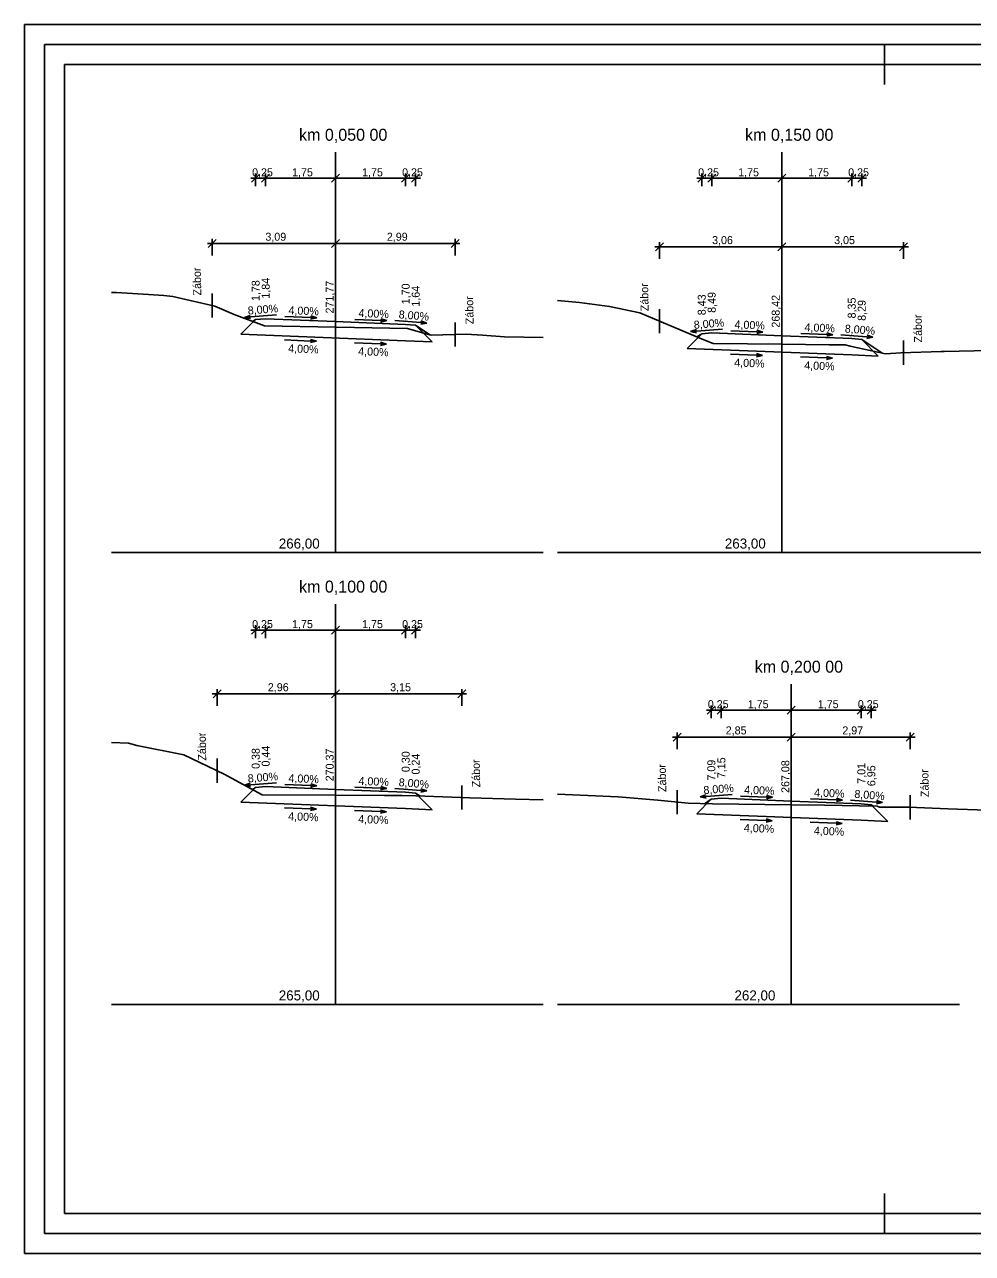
# Model space of a CAD drawing. Extents: x -763510.2 to -763467.2, y -1048902.9 to -1048872.2.
# Drawn here: x -763510.21 to -763486.51, y -1048902.88 to -1048872.18 of the extents above; entities that cross this region are included whole.
import ezdxf

# ---------------------------------------------------------------- set-up
doc = ezdxf.new("R2010")
doc.units = 0
for name, color, linetype in [('C3D-KORIDOR-SPOJNICE', 7, 'Continuous'), ('C3D-POPIS', 7, 'Continuous'), ('C3D-PR-POPIS-TEREN', 7, 'Continuous'), ('C3D-PR-TEREN', 7, 'Continuous'), ('C3D-ZOBPR-NADPIS', 7, 'Continuous'), ('C3D-ZOBPR-OSY', 7, 'Continuous'), ('C3D-ZOBPR-OSY-NADPIS', 7, 'Continuous'), ('Default', 7, 'Continuous'), ('U_formát', 7, 'Continuous'), ('U_rozvržení_rámeček', 7, 'Continuous'), ('Z_Pomocná', 7, 'Continuous')]:
    doc.layers.add(name, color=color, linetype=linetype)

# ---------------------------------------------------------------- blocks, each defined once
blk = doc.blocks.new('_Oblique')
at = {"layer": 'Default'}
blk.add_line((-0.5, -0.5), (0.5, 0.5), dxfattribs=at)
blk = doc.blocks.new('_Open30')
at = {"layer": 'Default'}
for p, q in [((-1, 0.27), (0, 0)), ((0, 0), (-1, -0.27)), ((0, 0), (-1, 0))]:
    blk.add_line(p, q, dxfattribs=at)
blk = doc.blocks.new('U1096')
at = {"layer": 'Default'}
for p, q in [((-420, 0), (-420, -10)), ((-210, 0), (-210, -10)), ((-420, -297), (-420, -287)), ((-210, -297), (-210, -287)), ((-420, -297), (-410, -297))]:
    blk.add_line(p, q, dxfattribs=at)
blk.add_lwpolyline([(0, -297), (0, 0), (-420, 0), (-420, -297)], close=True, dxfattribs=at)
at = {"layer": 'U_formát'}
for points in [[(-425, 5), (5, 5), (5, -302), (-425, -302)], [(-5, -292), (-5, -5), (-415, -5), (-415, -292)]]:
    blk.add_lwpolyline(points, close=True, dxfattribs=at)

msp = doc.modelspace()

# ---------------------------------------------------------------- linework, layer by layer
at = {"layer": 'C3D-KORIDOR-SPOJNICE'}
for p, q in [((-763504.434, -1048879.555), (-763504.8, -1048879.92)), ((-763504.434, -1048879.555), (-763504.507, -1048879.604)), ((-763504.184, -1048879.535), (-763504.434, -1048879.555)), ((-763502.434, -1048879.605), (-763504.184, -1048879.535)), ((-763502.434, -1048879.605), (-763500.684, -1048879.675)), ((-763504.8, -1048879.92), (-763500.684, -1048880.085)), ((-763500.684, -1048879.675), (-763500.434, -1048879.695)), ((-763500.434, -1048879.695), (-763500.018, -1048880.112)), ((-763500.434, -1048879.695), (-763500.077, -1048879.933)), ((-763493.283, -1048879.909), (-763493.649, -1048880.275)), ((-763493.283, -1048879.909), (-763493.403, -1048879.989)), ((-763493.033, -1048879.889), (-763493.283, -1048879.909)), ((-763491.283, -1048879.959), (-763493.033, -1048879.889)), ((-763500.018, -1048880.112), (-763500.684, -1048880.085)), ((-763491.283, -1048879.959), (-763489.533, -1048880.029)), ((-763489.533, -1048880.029), (-763489.283, -1048880.049)), ((-763489.283, -1048880.049), (-763488.867, -1048880.466)), ((-763489.283, -1048880.049), (-763488.776, -1048880.388)), ((-763493.649, -1048880.275), (-763489.533, -1048880.439)), ((-763488.867, -1048880.466), (-763489.533, -1048880.439)), ((-763504.434, -1048891.243), (-763504.8, -1048891.609)), ((-763504.434, -1048891.243), (-763504.514, -1048891.296)), ((-763504.184, -1048891.223), (-763504.434, -1048891.243)), ((-763502.434, -1048891.293), (-763504.184, -1048891.223)), ((-763502.434, -1048891.293), (-763500.684, -1048891.363)), ((-763500.684, -1048891.363), (-763500.434, -1048891.383)), ((-763500.434, -1048891.383), (-763500.018, -1048891.8)), ((-763500.434, -1048891.383), (-763500.327, -1048891.455)), ((-763493.042, -1048891.534), (-763493.408, -1048891.9)), ((-763493.042, -1048891.534), (-763493.214, -1048891.649)), ((-763492.792, -1048891.514), (-763493.042, -1048891.534)), ((-763491.042, -1048891.584), (-763492.792, -1048891.514)), ((-763491.042, -1048891.584), (-763489.292, -1048891.654)), ((-763504.8, -1048891.609), (-763500.684, -1048891.773)), ((-763500.018, -1048891.8), (-763500.684, -1048891.773)), ((-763493.408, -1048891.9), (-763489.292, -1048892.064)), ((-763489.292, -1048891.654), (-763489.042, -1048891.674)), ((-763489.042, -1048891.674), (-763488.626, -1048892.091)), ((-763489.042, -1048891.674), (-763488.987, -1048891.711)), ((-763488.626, -1048892.091), (-763489.292, -1048892.064))]:
    msp.add_line(p, q, dxfattribs=at)
at = {"layer": 'C3D-POPIS'}
for p, q in [((-763504.434, -1048876.224), (-763504.434, -1048875.904)), ((-763504.184, -1048876.224), (-763504.184, -1048875.904)), ((-763502.434, -1048876.224), (-763502.434, -1048875.904)), ((-763500.684, -1048876.224), (-763500.684, -1048875.904)), ((-763500.434, -1048876.224), (-763500.434, -1048875.904)), ((-763493.283, -1048876.224), (-763493.283, -1048875.904)), ((-763493.033, -1048876.224), (-763493.033, -1048875.904)), ((-763491.283, -1048876.224), (-763491.283, -1048875.904)), ((-763489.533, -1048876.224), (-763489.533, -1048875.904)), ((-763489.283, -1048876.224), (-763489.283, -1048875.904)), ((-763504.554, -1048876.024), (-763502.314, -1048876.024)), ((-763502.554, -1048876.024), (-763500.314, -1048876.024)), ((-763493.403, -1048876.024), (-763491.163, -1048876.024)), ((-763491.403, -1048876.024), (-763489.163, -1048876.024)), ((-763504.434, -1048887.513), (-763504.434, -1048887.193)), ((-763504.184, -1048887.513), (-763504.184, -1048887.193)), ((-763502.434, -1048887.513), (-763502.434, -1048887.193)), ((-763500.684, -1048887.513), (-763500.684, -1048887.193)), ((-763500.434, -1048887.513), (-763500.434, -1048887.193)), ((-763504.554, -1048887.313), (-763502.314, -1048887.313)), ((-763502.554, -1048887.313), (-763500.314, -1048887.313)), ((-763493.162, -1048889.313), (-763490.922, -1048889.313)), ((-763493.042, -1048889.513), (-763493.042, -1048889.193)), ((-763492.792, -1048889.513), (-763492.792, -1048889.193)), ((-763491.162, -1048889.313), (-763488.922, -1048889.313)), ((-763491.042, -1048889.513), (-763491.042, -1048889.193)), ((-763489.292, -1048889.513), (-763489.292, -1048889.193)), ((-763489.042, -1048889.513), (-763489.042, -1048889.193))]:
    msp.add_line(p, q, dxfattribs=at)
for points in [[(-763504.564, -1048879.49), (-763503.916, -1048879.438)], [(-763503.056, -1048879.505), (-763503.706, -1048879.479)], [(-763501.306, -1048879.575), (-763501.956, -1048879.549)], [(-763500.304, -1048879.63), (-763500.952, -1048879.578)], [(-763493.413, -1048879.844), (-763492.765, -1048879.793)], [(-763491.905, -1048879.859), (-763492.555, -1048879.833)], [(-763490.155, -1048879.929), (-763490.805, -1048879.903)], [(-763503.063, -1048880.09), (-763503.713, -1048880.064)], [(-763501.313, -1048880.16), (-763501.963, -1048880.134)], [(-763489.153, -1048879.984), (-763489.801, -1048879.933)], [(-763491.912, -1048880.444), (-763492.562, -1048880.418)], [(-763490.162, -1048880.514), (-763490.812, -1048880.488)], [(-763504.564, -1048891.179), (-763503.916, -1048891.127)], [(-763503.056, -1048891.193), (-763503.706, -1048891.167)], [(-763501.306, -1048891.263), (-763501.956, -1048891.237)], [(-763500.304, -1048891.319), (-763500.952, -1048891.267)], [(-763493.173, -1048891.469), (-763492.525, -1048891.418)], [(-763491.665, -1048891.484), (-763492.314, -1048891.458)], [(-763489.915, -1048891.554), (-763490.564, -1048891.528)], [(-763488.912, -1048891.609), (-763489.56, -1048891.558)], [(-763503.063, -1048891.778), (-763503.713, -1048891.752)], [(-763501.313, -1048891.848), (-763501.963, -1048891.822)], [(-763491.672, -1048892.069), (-763492.321, -1048892.043)], [(-763489.922, -1048892.139), (-763490.571, -1048892.113)]]:
    msp.add_lwpolyline(points, dxfattribs=at)
at = {"layer": 'C3D-PR-TEREN'}
for points in [[(-763508.038, -1048878.875), (-763507.915, -1048878.879), (-763507.116, -1048878.927), (-763506.733, -1048878.954), (-763506.504, -1048878.982), (-763505.458, -1048879.218), (-763504.973, -1048879.43), (-763504.211, -1048879.714), (-763502.434, -1048879.746), (-763501.963, -1048879.754), (-763500.634, -1048879.775), (-763500.266, -1048879.888), (-763500.042, -1048879.941), (-763499.171, -1048879.918), (-763498.762, -1048879.94), (-763498.214, -1048879.989), (-763497.246, -1048880.002)], [(-763496.887, -1048879.077), (-763496.334, -1048879.124), (-763495.584, -1048879.224), (-763494.83, -1048879.39), (-763493.229, -1048880.061), (-763492.998, -1048880.148), (-763491.283, -1048880.169), (-763490.093, -1048880.184), (-763489.693, -1048880.187), (-763489.569, -1048880.215), (-763488.688, -1048880.407), (-763488.306, -1048880.383), (-763487.299, -1048880.356), (-763487.225, -1048880.356), (-763486.095, -1048880.331)], [(-763508.038, -1048890.123), (-763507.615, -1048890.137), (-763507.403, -1048890.198), (-763506.228, -1048890.425), (-763505.223, -1048890.908), (-763504.27, -1048891.43), (-763502.434, -1048891.438), (-763501.211, -1048891.444), (-763500.78, -1048891.441), (-763500.43, -1048891.451), (-763499.08, -1048891.502), (-763497.94, -1048891.54), (-763497.246, -1048891.551)], [(-763496.887, -1048891.415), (-763495.367, -1048891.474), (-763494.381, -1048891.564), (-763493.619, -1048891.634), (-763493.016, -1048891.656), (-763491.042, -1048891.68), (-763490.216, -1048891.69), (-763488.9, -1048891.713), (-763488.84, -1048891.735), (-763488.575, -1048891.732), (-763488.102, -1048891.738), (-763487.13, -1048891.778), (-763485.901, -1048891.816), (-763485.569, -1048891.814)]]:
    msp.add_lwpolyline(points, dxfattribs=at)
at = {"layer": 'C3D-ZOBPR-OSY'}
for p, q in [((-763502.434, -1048885.374), (-763502.434, -1048875.374)), ((-763491.283, -1048885.374), (-763491.283, -1048875.374)), ((-763508.038, -1048885.374), (-763497.246, -1048885.374)), ((-763496.887, -1048885.374), (-763486.095, -1048885.374)), ((-763502.434, -1048896.663), (-763502.434, -1048886.663)), ((-763491.042, -1048896.663), (-763491.042, -1048888.663)), ((-763508.038, -1048896.663), (-763497.246, -1048896.663)), ((-763496.887, -1048896.663), (-763486.84, -1048896.663))]:
    msp.add_line(p, q, dxfattribs=at)
at = {"layer": 'Default'}
for p, q in [((-763502.434, -1048877.355), (-763502.434, -1048877.775)), ((-763502.434, -1048877.355), (-763502.434, -1048877.775)), ((-763491.283, -1048877.439), (-763491.283, -1048877.859)), ((-763491.283, -1048877.439), (-763491.283, -1048877.859)), ((-763505.641, -1048877.655), (-763502.314, -1048877.655)), ((-763505.521, -1048877.955), (-763505.521, -1048877.535)), ((-763502.554, -1048877.655), (-763499.327, -1048877.655)), ((-763499.447, -1048877.955), (-763499.447, -1048877.535)), ((-763494.458, -1048877.739), (-763491.163, -1048877.739)), ((-763494.338, -1048878.039), (-763494.338, -1048877.619)), ((-763491.403, -1048877.739), (-763488.114, -1048877.739)), ((-763488.234, -1048878.039), (-763488.234, -1048877.619)), ((-763505.398, -1048889.208), (-763505.398, -1048888.788)), ((-763502.434, -1048888.608), (-763502.434, -1048889.028)), ((-763502.434, -1048888.608), (-763502.434, -1048889.028)), ((-763499.283, -1048889.208), (-763499.283, -1048888.788)), ((-763505.518, -1048888.908), (-763502.314, -1048888.908)), ((-763502.554, -1048888.908), (-763499.163, -1048888.908)), ((-763491.042, -1048889.688), (-763491.042, -1048890.108)), ((-763491.042, -1048889.688), (-763491.042, -1048890.108)), ((-763494.015, -1048889.988), (-763490.922, -1048889.988)), ((-763493.895, -1048890.288), (-763493.895, -1048889.868)), ((-763491.162, -1048889.988), (-763487.948, -1048889.988)), ((-763488.068, -1048890.288), (-763488.068, -1048889.868))]:
    msp.add_line(p, q, dxfattribs=at)
at = {"layer": 'Z_Pomocná'}
for points in [[(-763505.521, -1048879.504), (-763505.521, -1048879.204), (-763505.521, -1048878.904)], [(-763494.338, -1048879.897), (-763494.338, -1048879.597), (-763494.338, -1048879.297)], [(-763499.447, -1048880.226), (-763499.447, -1048879.926), (-763499.447, -1048879.626)], [(-763488.234, -1048880.681), (-763488.234, -1048880.381), (-763488.234, -1048880.081)], [(-763505.398, -1048891.124), (-763505.398, -1048890.824), (-763505.398, -1048890.524)], [(-763499.283, -1048891.795), (-763499.283, -1048891.495), (-763499.283, -1048891.195)], [(-763493.895, -1048891.908), (-763493.895, -1048891.608), (-763493.895, -1048891.308)], [(-763488.068, -1048892.04), (-763488.068, -1048891.74), (-763488.068, -1048891.44)]]:
    msp.add_lwpolyline(points, dxfattribs=at)

# ---------------------------------------------------------------- block references
at = {"layer": 'C3D-POPIS'}
for name, p, xscale, yscale, rotation in [('_Oblique', (-763504.434, -1048876.024), 0.2, 0.20000000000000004, 180), ('_Oblique', (-763504.184, -1048876.024), 0.2, 0.20000000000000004, 180), ('_Oblique', (-763502.434, -1048876.024), 0.2, 0.20000000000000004, 180), ('_Oblique', (-763493.283, -1048876.024), 0.2, 0.20000000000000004, 180), ('_Oblique', (-763493.033, -1048876.024), 0.2, 0.20000000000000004, 180), ('_Oblique', (-763491.283, -1048876.024), 0.2, 0.20000000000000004, 180), ('_Open30', (-763504.714, -1048879.502), 0.14999999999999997, 0.15, -175.426078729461), ('_Open30', (-763502.907, -1048879.511), 0.15000000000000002, 0.15000000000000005, -2.290610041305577), ('_Open30', (-763501.157, -1048879.581), 0.15000000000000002, 0.15000000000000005, -2.290610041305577), ('_Open30', (-763500.154, -1048879.642), 0.15, 0.15, -4.573921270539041), ('_Open30', (-763493.563, -1048879.856), 0.14999999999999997, 0.15, -175.42607872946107), ('_Open30', (-763491.756, -1048879.865), 0.15000000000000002, 0.15000000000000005, -2.290610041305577), ('_Open30', (-763490.006, -1048879.935), 0.15000000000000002, 0.15000000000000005, -2.290610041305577), ('_Open30', (-763502.914, -1048880.096), 0.15000000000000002, 0.15000000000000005, -2.290610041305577), ('_Open30', (-763501.164, -1048880.166), 0.15000000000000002, 0.15000000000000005, -2.290610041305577), ('_Open30', (-763489.003, -1048879.996), 0.15, 0.15, -4.573921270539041), ('_Open30', (-763491.762, -1048880.45), 0.15000000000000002, 0.15000000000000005, -2.290610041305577), ('_Open30', (-763490.012, -1048880.52), 0.15000000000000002, 0.15000000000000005, -2.290610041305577), ('_Oblique', (-763504.434, -1048887.313), 0.2, 0.20000000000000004, 180), ('_Oblique', (-763504.184, -1048887.313), 0.2, 0.20000000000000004, 180), ('_Oblique', (-763502.434, -1048887.313), 0.2, 0.20000000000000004, 180), ('_Oblique', (-763493.042, -1048889.313), 0.2, 0.20000000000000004, 180), ('_Oblique', (-763492.792, -1048889.313), 0.2, 0.20000000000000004, 180), ('_Oblique', (-763491.042, -1048889.313), 0.2, 0.20000000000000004, 180), ('_Open30', (-763504.714, -1048891.19), 0.15, 0.15, -175.42607879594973), ('_Open30', (-763502.907, -1048891.199), 0.15000000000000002, 0.15000000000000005, -2.290610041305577), ('_Open30', (-763501.157, -1048891.269), 0.15000000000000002, 0.15000000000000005, -2.290610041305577), ('_Open30', (-763500.154, -1048891.33), 0.15, 0.15, -4.573921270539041), ('_Open30', (-763493.322, -1048891.481), 0.14999999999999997, 0.15, -175.42607872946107), ('_Open30', (-763491.515, -1048891.49), 0.15000000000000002, 0.15000000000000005, -2.290610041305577), ('_Open30', (-763489.765, -1048891.56), 0.15000000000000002, 0.15000000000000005, -2.290610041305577), ('_Open30', (-763488.763, -1048891.621), 0.15, 0.15, -4.573921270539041), ('_Open30', (-763502.914, -1048891.784), 0.15000000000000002, 0.15000000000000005, -2.290610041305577), ('_Open30', (-763501.164, -1048891.854), 0.15000000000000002, 0.15000000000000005, -2.290610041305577), ('_Open30', (-763491.522, -1048892.075), 0.15000000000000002, 0.15000000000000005, -2.290610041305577), ('_Open30', (-763489.772, -1048892.145), 0.15000000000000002, 0.15000000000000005, -2.290610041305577)]:
    msp.add_blockref(name, p, dxfattribs=dict(at, xscale=xscale, yscale=yscale, rotation=rotation))
at = {"layer": 'C3D-POPIS', "xscale": 0.2, "yscale": 0.20000000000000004}
for p in [(-763502.434, -1048876.024), (-763500.684, -1048876.024), (-763500.434, -1048876.024), (-763491.283, -1048876.024), (-763489.533, -1048876.024), (-763489.283, -1048876.024), (-763502.434, -1048887.313), (-763500.684, -1048887.313), (-763500.434, -1048887.313), (-763491.042, -1048889.313), (-763489.292, -1048889.313), (-763489.042, -1048889.313)]:
    msp.add_blockref('_Oblique', p, dxfattribs=at)
at = {"layer": 'Default', "xscale": 0.2, "yscale": 0.20000000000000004, "rotation": 180}
for p in [(-763505.521, -1048877.655), (-763502.434, -1048877.655), (-763494.338, -1048877.739), (-763491.283, -1048877.739), (-763505.398, -1048888.908), (-763502.434, -1048888.908), (-763493.895, -1048889.988), (-763491.042, -1048889.988)]:
    msp.add_blockref('_Oblique', p, dxfattribs=at)
at = {"layer": 'Default', "xscale": 0.2, "yscale": 0.20000000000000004}
for p in [(-763502.434, -1048877.655), (-763499.447, -1048877.655), (-763491.283, -1048877.739), (-763488.234, -1048877.739), (-763502.434, -1048888.908), (-763499.283, -1048888.908), (-763491.042, -1048889.988), (-763488.068, -1048889.988)]:
    msp.add_blockref('_Oblique', p, dxfattribs=at)
at = {"layer": 'U_rozvržení_rámeček', "xscale": 0.1, "yscale": 0.10000000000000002}
msp.add_blockref('U1096', (-763467.711, -1048872.685), dxfattribs=at)

# ---------------------------------------------------------------- texts
at = {"layer": 'C3D-POPIS'}
for s, p in [('0,25', (-763504.522, -1048875.975)), ('1,75', (-763503.522, -1048875.975)), ('1,75', (-763501.772, -1048875.975)), ('0,25', (-763500.772, -1048875.975)), ('0,25', (-763493.371, -1048875.975)), ('1,75', (-763492.371, -1048875.975)), ('1,75', (-763490.621, -1048875.975)), ('0,25', (-763489.621, -1048875.975)), ('0,25', (-763504.522, -1048887.263)), ('1,75', (-763503.522, -1048887.263)), ('1,75', (-763501.772, -1048887.263)), ('0,25', (-763500.772, -1048887.263)), ('0,25', (-763493.13, -1048889.263)), ('1,75', (-763492.13, -1048889.263)), ('1,75', (-763490.38, -1048889.263)), ('0,25', (-763489.38, -1048889.263))]:
    msp.add_text(s, height=0.2, dxfattribs=at).set_placement(p)
for s, rotation, p in [('1,78', 90, (-763504.333, -1048879.092)), ('1,84', 90, (-763504.083, -1048879.032)), ('271,77', 90, (-763502.483, -1048879.402)), ('271,77', 90, (-763502.483, -1048879.402)), ('1,70', 90, (-763500.583, -1048879.172)), ('1,64', 90, (-763500.333, -1048879.232)), ('8,43', 90, (-763493.182, -1048879.446)), ('8,49', 90, (-763492.932, -1048879.386)), ('268,42', 90, (-763491.332, -1048879.756)), ('268,42', 90, (-763491.332, -1048879.756)), ('8,00%', 4.5837, (-763504.623, -1048879.431)), ('4,00%', 357.7082, (-763503.616, -1048879.419)), ('4,00%', 357.7082, (-763501.866, -1048879.489)), ('8,35', 90, (-763489.432, -1048879.526)), ('8,29', 90, (-763489.182, -1048879.586)), ('8,00%', 355.4163, (-763500.863, -1048879.522)), ('8,00%', 4.5837, (-763493.472, -1048879.786)), ('4,00%', 357.7082, (-763492.465, -1048879.773)), ('4,00%', 357.7082, (-763490.715, -1048879.843)), ('8,00%', 355.4163, (-763489.712, -1048879.876)), ('4,00%', 357.7094, (-763503.623, -1048880.371)), ('4,00%', 357.7094, (-763501.873, -1048880.441)), ('4,00%', 357.7094, (-763492.472, -1048880.725)), ('4,00%', 357.7094, (-763490.722, -1048880.795)), ('0,38', 90, (-763504.333, -1048890.78)), ('0,44', 90, (-763504.083, -1048890.72)), ('270,37', 90, (-763502.483, -1048891.09)), ('270,37', 90, (-763502.483, -1048891.09)), ('0,30', 90, (-763500.583, -1048890.86)), ('0,24', 90, (-763500.333, -1048890.92)), ('7,09', 90, (-763492.942, -1048891.071)), ('7,15', 90, (-763492.692, -1048891.011)), ('267,08', 90, (-763491.092, -1048891.381)), ('267,08', 90, (-763491.092, -1048891.381)), ('7,01', 90, (-763489.192, -1048891.151)), ('8,00%', 4.5837, (-763504.623, -1048891.12)), ('4,00%', 357.7082, (-763503.616, -1048891.108)), ('6,95', 90, (-763488.942, -1048891.211)), ('4,00%', 357.7082, (-763501.866, -1048891.178)), ('8,00%', 355.4163, (-763500.863, -1048891.21)), ('8,00%', 4.5837, (-763493.231, -1048891.411)), ('4,00%', 357.7082, (-763492.225, -1048891.398)), ('4,00%', 357.7082, (-763490.475, -1048891.468)), ('8,00%', 355.4163, (-763489.472, -1048891.501)), ('4,00%', 357.7094, (-763503.623, -1048892.059)), ('4,00%', 357.7094, (-763501.873, -1048892.129)), ('4,00%', 357.7094, (-763492.231, -1048892.35)), ('4,00%', 357.7094, (-763490.481, -1048892.42))]:
    msp.add_text(s, height=0.2, rotation=rotation, dxfattribs=at).set_placement(p)
at = {"layer": 'C3D-PR-POPIS-TEREN'}
for p in [(-763505.792, -1048878.951), (-763494.609, -1048879.344), (-763498.984, -1048879.669), (-763487.771, -1048880.125), (-763505.669, -1048890.571), (-763498.819, -1048891.238), (-763494.167, -1048891.356), (-763487.604, -1048891.483)]:
    msp.add_text('Zábor', height=0.2, rotation=91.1271, dxfattribs=at).set_placement(p)
at = {"layer": 'C3D-ZOBPR-NADPIS'}
for s, p in [('km 0,050 00', (-763503.349, -1048875.087)), ('km 0,150 00', (-763492.198, -1048875.087)), ('km 0,100 00', (-763503.349, -1048886.376)), ('km 0,200 00', (-763491.957, -1048888.376))]:
    msp.add_text(s, height=0.3, rotation=360, dxfattribs=at).set_placement(p)
at = {"layer": 'C3D-ZOBPR-OSY-NADPIS'}
for s, p in [('266,00', (-763503.855, -1048885.275)), ('263,00', (-763492.704, -1048885.275)), ('265,00', (-763503.855, -1048896.564)), ('262,00', (-763492.463, -1048896.564))]:
    msp.add_text(s, height=0.25, rotation=360, dxfattribs=at).set_placement(p)
at = {"layer": 'Default'}
for s, p in [('3,09', (-763504.19, -1048877.585)), ('2,99', (-763501.153, -1048877.585)), ('3,06', (-763493.023, -1048877.669)), ('3,05', (-763489.972, -1048877.669)), ('2,96', (-763504.128, -1048888.839)), ('3,15', (-763501.071, -1048888.839)), ('2,85', (-763492.682, -1048889.918)), ('2,97', (-763489.767, -1048889.918))]:
    msp.add_text(s, height=0.2, dxfattribs=at).set_placement(p)

doc.saveas('drawing.dxf')
